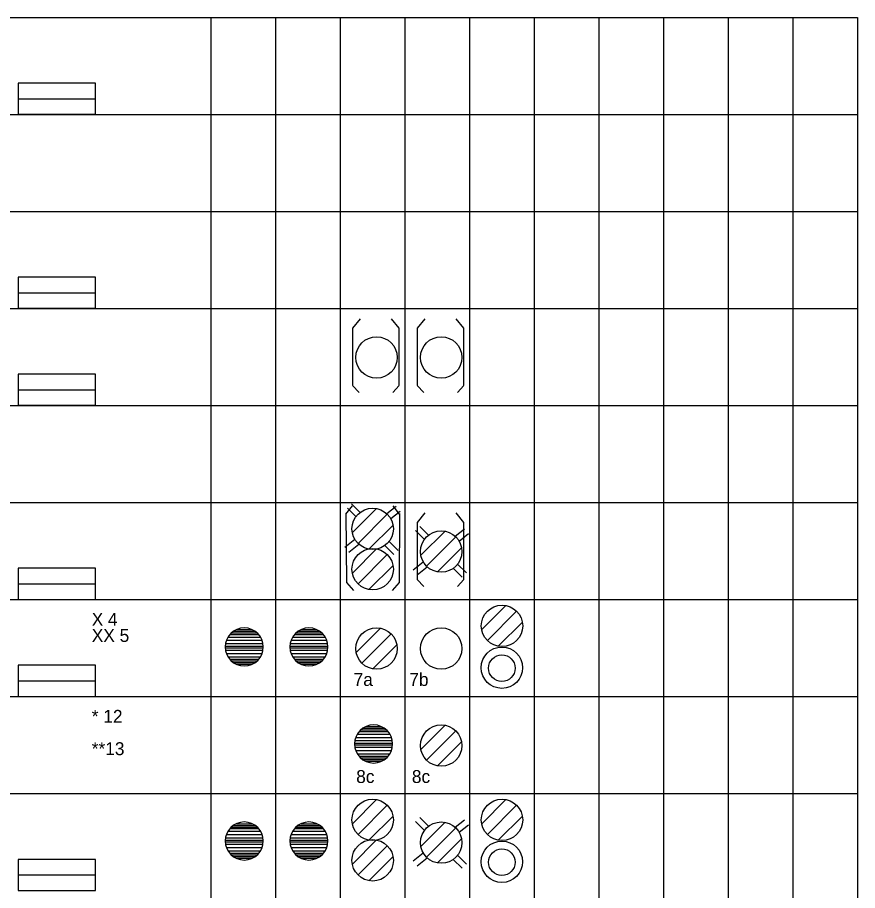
# Model space of a CAD drawing. Extents: x -28 to 822, y 61 to 665.
# Drawn here: x 460.7 to 590.6, y 246.8 to 381.7 of the extents above; entities that cross this region are included whole.
import ezdxf

# ---------------------------------------------------------------- set-up
doc = ezdxf.new("R2010")
doc.units = 0
doc.layers.add('KOLEJIŠTĚ', color=7, linetype='Continuous')
doc.layers.add('nové', color=7, linetype='Continuous')

# ---------------------------------------------------------------- blocks, each defined once
blk = doc.blocks.new('ZT18')
for p, q in [((10, 6), (0, 6)), ((0, 6), (0, 2)), ((10, 2), (10, 6)), ((0, 2), (10, 2))]:
    blk.add_line(p, q)
blk.add_lwpolyline([(0, 4), (0, 4), (10, 4)])
blk = doc.blocks.new('ZT95')
for p, q in [((2.793, 4.073), (0.927, 2.207)), ((3.631, 3.631), (1.369, 1.369)), ((4.073, 2.793), (2.207, 0.927))]:
    blk.add_line(p, q)
blk.add_circle((2.5, 2.5), 1.6)
blk = doc.blocks.new('HR6')
for p, q in [((-1.96, 1.2), (1.96, 1.2)), ((-1.75, 1.49), (1.75, 1.49)), ((-1.56, 1.69), (1.56, 1.69)), ((-1.3, 1.89), (1.3, 1.89)), ((-0.95, 2.09), (0.95, 2.09)), ((-2.26, 0.4), (2.26, 0.4)), ((-2.2, 0.09), (2.2, 0.09)), ((-2.16, 0.8), (2.16, 0.8)), ((-2.26, -0.4), (2.26, -0.4)), ((-2.2, -0.09), (2.2, -0.09)), ((-2.16, -0.8), (2.16, -0.8)), ((-1.96, -1.2), (1.96, -1.2)), ((-1.75, -1.49), (1.75, -1.49)), ((-1.56, -1.69), (1.56, -1.69)), ((-1.3, -1.89), (1.3, -1.89)), ((-0.95, -2.09), (0.95, -2.09))]:
    blk.add_line(p, q)
for start, end in [(0, 180), (180, 0)]:
    blk.add_arc((0, 0), 2.3, start, end)
blk = doc.blocks.new('ZT94')
at = {"xscale": 0.6400000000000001, "yscale": 0.6400000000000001}
blk.add_blockref('HR6', (2.5, 2.5), dxfattribs=at)

msp = doc.modelspace()

# ---------------------------------------------------------------- linework, layer by layer
for p, q in [((5.07, 381.74), (540.62, 381.74)), ((490.62, 381.74), (490.62, 111.74)), ((500.62, 381.74), (500.62, 111.74)), ((510.62, 381.74), (510.62, 111.74)), ((520.62, 381.74), (520.62, 111.74)), ((530.62, 381.74), (530.62, 111.74)), ((560.62, 381.74), (560.62, 111.74)), ((339.09, 366.74), (540.62, 366.74)), ((5.07, 351.74), (540.62, 351.74)), ((5.07, 336.74), (540.62, 336.74)), ((512.55, 333.68), (513.75, 335.15)), ((519.73, 333.68), (518.53, 335.15)), ((522.55, 333.68), (523.75, 335.15)), ((529.73, 333.68), (528.53, 335.15)), ((512.55, 324.87), (512.55, 333.68)), ((519.73, 324.87), (519.73, 333.68)), ((522.55, 324.87), (522.55, 333.68)), ((529.73, 324.87), (529.73, 333.68)), ((512.53, 324.84), (513.53, 323.76)), ((519.75, 324.84), (518.75, 323.76)), ((522.53, 324.84), (523.53, 323.76)), ((529.75, 324.84), (528.75, 323.76)), ((339.09, 321.74), (540.62, 321.74)), ((5.07, 306.74), (540.62, 306.74)), ((513.73, 305.19), (512.37, 306.55)), ((511.51, 304.96), (512.51, 306.26)), ((513.08, 304.53), (511.72, 305.9)), ((517.82, 305.03), (519.27, 306.19)), ((518.44, 304.27), (519.89, 305.43)), ((519.8, 304.96), (518.8, 306.26)), ((522.55, 303.68), (523.75, 305.15)), ((529.73, 303.68), (528.53, 305.15)), ((511.51, 305.04), (511.59, 294.38)), ((519.8, 305.04), (519.73, 294.38)), ((523.64, 301.05), (522.28, 302.41)), ((522.55, 294.87), (522.55, 303.68)), ((524.29, 301.71), (522.93, 303.06)), ((528.39, 301.54), (529.83, 302.7)), ((529.73, 294.87), (529.73, 303.68)), ((511.33, 299.83), (512.89, 301.08)), ((529, 300.78), (530.45, 301.94)), ((511.94, 299.06), (513.5, 300.31)), ((518.92, 298.69), (517.55, 300.06)), ((519.57, 299.35), (518.21, 300.71)), ((521.89, 296.35), (523.45, 297.6)), ((530.13, 295.86), (528.77, 297.22)), ((522.5, 295.58), (524.06, 296.83)), ((529.48, 295.21), (528.11, 296.58)), ((511.59, 294.38), (512.66, 293.15)), ((519.73, 294.38), (518.65, 293.15)), ((522.53, 294.84), (523.53, 293.76)), ((529.75, 294.84), (528.75, 293.76)), ((5.07, 291.74), (540.62, 291.74)), ((339.09, 276.74), (540.62, 276.74)), ((5.07, 261.74), (540.62, 261.74)), ((524.29, 256.71), (522.93, 258.06)), ((523.64, 256.05), (522.28, 257.41)), ((528.39, 256.54), (529.83, 257.7)), ((529, 255.78), (530.45, 256.94)), ((521.89, 251.35), (523.45, 252.6)), ((522.5, 250.58), (524.06, 251.83)), ((529.48, 250.21), (528.11, 251.58)), ((530.13, 250.86), (528.77, 252.22))]:
    msp.add_line(p, q)
for centre, radius in [((516.24, 329.17), 3.2), ((516.24, 329.17), 3.2), ((526.24, 329.17), 3.2), ((526.24, 284.17), 3.2), ((535.62, 281.21), 3.2), ((535.62, 281.14), 2.06), ((535.62, 251.21), 3.2), ((535.62, 251.14), 2.06)]:
    msp.add_circle(centre, radius)
at = {"layer": 'nové'}
for p, q in [((540.62, 381.74), (540.62, 111.74)), ((540.62, 381.74), (590.62, 381.74)), ((550.62, 381.74), (550.62, 111.74)), ((570.62, 381.74), (570.62, 111.74)), ((580.62, 381.74), (580.62, 111.74)), ((590.62, 381.74), (590.62, 111.74)), ((540.62, 366.74), (590.62, 366.74)), ((540.62, 351.74), (590.62, 351.74)), ((540.62, 336.74), (590.62, 336.74)), ((540.62, 321.74), (590.62, 321.74)), ((540.62, 306.74), (590.62, 306.74)), ((540.62, 291.74), (590.62, 291.74)), ((540.62, 276.74), (590.62, 276.74)), ((540.62, 261.74), (590.62, 261.74))]:
    msp.add_line(p, q, dxfattribs=at)

# ---------------------------------------------------------------- block references
at = {"layer": 'KOLEJIŠTĚ'}
for name, p, xscale, yscale in [('ZT18', (460.8, 364.38), 1.2000000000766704, 1.2000000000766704), ('ZT18', (460.8, 334.38), 1.2000000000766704, 1.2000000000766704), ('ZT18', (460.8, 319.38), 1.2000000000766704, 1.2000000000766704), ('ZT95', (510.64, 297.68), 2, 2), ('ZT95', (521.24, 294.17), 2, 2), ('ZT95', (510.64, 291.43), 2, 2), ('ZT18', (460.8, 289.38), 1.2000000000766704, 1.2000000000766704), ('ZT95', (530.64, 282.68), 2, 2), ('ZT94', (490.78, 279.42), 2, 2), ('ZT94', (500.78, 279.42), 2, 2), ('ZT95', (511.24, 279.17), 2, 2), ('ZT18', (460.8, 274.38), 1.2000000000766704, 1.2000000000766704), ('ZT94', (510.78, 264.42), 2, 2), ('ZT95', (521.24, 264.17), 2, 2), ('ZT95', (510.64, 252.68), 2, 2), ('ZT95', (530.64, 252.68), 2, 2), ('ZT94', (490.78, 249.42), 2, 2), ('ZT94', (500.78, 249.42), 2, 2), ('ZT95', (521.24, 249.17), 2, 2), ('ZT95', (510.64, 246.43), 2, 2), ('ZT18', (460.8, 244.38), 1.2000000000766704, 1.2000000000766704)]:
    msp.add_blockref(name, p, dxfattribs=dict(at, xscale=xscale, yscale=yscale))

# ---------------------------------------------------------------- texts
for s, p in [('X', (472.2, 287.69)), ('4', (474.7, 287.69)), ('XX 5', (472.2, 285.19)), ('7a', (512.69, 278.39)), ('7b', (521.3, 278.39)), ('* 12', (472.2, 272.69)), ('**13', (472.2, 267.69)), ('8c', (513.09, 263.39)), ('8c', (521.7, 263.39))]:
    msp.add_text(s, height=2).set_placement(p)

doc.saveas('drawing.dxf')
